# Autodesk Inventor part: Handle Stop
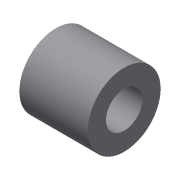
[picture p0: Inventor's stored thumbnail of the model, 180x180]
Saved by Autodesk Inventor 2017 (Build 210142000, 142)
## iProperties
Shininess: 77.0
Length Units: 11269
Angle Units: 11279
Time Units: 11290
Mass Units: 11283
Length Display Precision: 3
Angle Display Precision: 2
Compacted: True
Created: 2002-02
Part Number: Handle Stop
Document SubType Name: Modeling
Designer: ***
Density: 1 g/cm^3
Material: Generic
Mass: 2.36248 g
Surface Area: 14.8283 cm^2
Volume: 2.36248 cm^3
Appearance: Default
Density: 0.0
Volumn: 0.0
Area: 0.0
PropertySet Name: Model Information
Control State: 0
Master: False
Checked Out: False
Author: ***
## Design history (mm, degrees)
sketch "Sketch1"
  geometry: L1 (0, 0)-(0, -2); L2 (0, -2)-(8, -2); L3 (8, -2)-(8, 13); L4 (8, 13)-(4, 13); L5 (4, 13)-(4, 0); L6 (4, 0)-(0, 0)
  constraints: 12 end point, 4 parallel, 1 perpendicular, 1 vertical
  dimensions: "d0" = 16 diameter of L3 L1; "d1" = 8 diameter of L5 L1; "d2" = 2 distance of L1.start L1.end; "d3" = 15 distance of L2.end L3.end
revolve "Revolution1" sketch "Sketch1" stored, may be unused: angle "d4" = 90 deg
body "Solid1"
